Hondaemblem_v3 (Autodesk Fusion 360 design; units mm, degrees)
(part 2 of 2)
extrude "Extrusion40" add of existing geometry blind 1
extrude "Extrusion41" add of existing geometry blind 1
extrude "Extrusion42" add of existing geometry blind 1
chamfer "Fase6" distance 2 Rotate Angle 80
delete_face "Fläche löschen17"
delete_face "Fläche löschen18"
delete_face "Fläche löschen19"
delete_face "Fläche löschen20"
delete_face "Fläche löschen21"
delete_face "Fläche löschen22"
extrude "Extrusion43" add of existing geometry blind 1
delete_face "Fläche löschen23"
delete_face "Fläche löschen24"
delete_face "Fläche löschen25"
delete_face "Fläche löschen26"
delete_face "Fläche löschen27"
delete_face "Fläche löschen28"
delete_face "Fläche löschen29"
delete_face "Fläche löschen30"
delete_face "Fläche löschen31"
delete_face "Fläche löschen32"
delete_face "Fläche löschen33"
delete_face "Fläche löschen34"
move "Verschieben18"
extrude "Extrusion46" sketch "Skizze1" blind -1
delete_face "Fläche löschen41"
delete_face "Fläche löschen42"
delete_face "Fläche löschen43"
delete_face "Fläche löschen44"
delete_face "Fläche löschen45"
delete_face "Fläche löschen46"
move "Verschieben19"
split "Teilen6"
extrude "Extrusion47" add of existing geometry blind 0.4
extrude "Extrusion48" add of existing geometry blind 0.2
combine "Kombinieren4"
move "Verschieben20"
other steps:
base_feature "Basiselement" bodies "Emblem (7)", "Emblem (6)", "Emblem (6) (1)"
named bodies: "Emblem", "Emblem (1)", "Emblem (2)", "Emblem (3)", "Emblem (4)", "Emblem (5)", "Emblem (6)", "Emblem (7)", "Emblem (8)", "Emblem (6) (1)", "Honda_innen"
